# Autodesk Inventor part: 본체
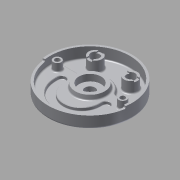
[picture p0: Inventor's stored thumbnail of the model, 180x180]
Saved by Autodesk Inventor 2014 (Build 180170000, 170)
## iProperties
Created: 2015-06
Part Number: 본체
Material: 알루미늄 6061
Document SubType Name: Modeling
Designer: MYHOME
Mass: 1071.21 g
Surface Area: 1035.4 cm^2
Volume: 395.281 cm^3
Density: 2.71 g/cm^3
Appearance: 알루미늄 - 평지
Author: MYHOME
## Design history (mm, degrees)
sketch "스케치1"
  geometry: C1 r 95 at (0, 0); C2 r 90 at (0, 0); 1 further point
  constraints: 2 centre point, 2 coincident
  dimensions: "d0" = 190 diameter of C1; "d1" = 180 diameter of C2
extrude "돌출1" new body sketch "스케치1" distance "d2" = 32; taper "d3" = 0 deg
extrude "돌출2" join sketch "스케치1" distance "d4" = 7; taper "d5" = 0 deg
sketch "스케치2"
  geometry: L1 (-88.566, 16)-(-38.833, 16); L2 (38.833, 16)-(88.566, 16); A1 r 90 centre (0, 0) between (-88.566, 16) and (88.566, 16) reference; A2 r 42 centre (0, 0) between (38.833, 16) and (-38.833, 16)
  constraints: 4 end point, 4 point on circle, 1 centre point, 1 coincident, 1 collinear, 1 horizontal
  dimensions: "d7" = 84 diameter of A2; "d8" = 16 distance from line of L2 A2.centre; "d9" = 16 distance from line of A1.centre L1
extrude "돌출3" join sketch "스케치2" distance "d10" = 7; taper "d11" = 0 deg
fillet "모깎기1" dims "d12" = 10
sketch "스케치3"
  geometry: C1 r 15 at (-40, 52); C2 r 15 at (40, 52); A1 r 90 centre (0, 0) between (85.114, 29.25) and (-85.114, 29.25) reference
  constraints: 2 centre point, 1 horizontal alignment
  dimensions: "d13" = 30 diameter of C1; "d14" = 30 diameter of C2; "d15" = 80 distance of C2.centre C1.centre; "d16" = 40 horizontal distance of A1.centre C2.centre; "d17" = 52 vertical distance of A1.centre C2.centre
extrude "돌출4" join sketch "스케치3" distance "d18" = 25; taper "d19" = 0 deg
sketch "스케치4"
  geometry: C1 r 15 at (0, 0) reference; C2 r 15 at (80, 0) reference; C3 r 10 at (80, 0); C4 r 10 at (0, 0); 1 further point
  constraints: 2 centre point, 2 coincident
  dimensions: "d20" = 20 diameter of C3; "d21" = 20 diameter of C4
extrude "돌출5" cut sketch "스케치4" stored distance "d22" = 25; taper "d23" = 0 deg
sketch "스케치5"
  geometry: L1 (6, -15)-(-6, -15); L2 (-6, -15)-(-6, 15); L3 (-6, 15)-(6, 15); L4 (6, 15)-(6, -15); L5 (6, -15)-(-6, 15); L6 (-6, -15)-(6, 15); L7 (95, -6)-(65, -6); L8 (65, -6)-(65, 6); L9 (65, 6)-(95, 6); L10 (95, 6)-(95, -6); L11 (95, -6)-(65, 6); L12 (65, -6)-(95, 6); C1 r 10 at (80, 0) reference; 5 further points
  constraints: 24 end point, 6 midpoint, 4 parallel, 2 horizontal, 2 perpendicular, 1 horizontal alignment, 1 vertical alignment, 2 other
  dimensions: "d24" = 12 distance between parallel lines of L7 L9; "d25" = 12 distance between parallel lines of L4 L2
extrude "돌출6" cut sketch "스케치5" distance "d26" = 3; taper "d27" = 0 deg
sketch "스케치6"
  geometry: L1 (-45.033, 16)-(-75.657, 16) reference; L2 (-59, -19)-(-41, -19); L3 (41, -19)-(59, -19); L4 (50, -19)-(50, -14); L5 (41, -19)-(41, -14); L6 (59, -19)-(59, -14); L7 (-50, -19)-(-50, -14); L8 (-41, -19)-(-41, -14); L9 (-59, -19)-(-59, -14); A1 r 90 centre (0, 0) between (-85.114, 29.25) and (85.114, 29.25) reference; A2 r 50 centre (0, -19) between (-50, -19) and (50, -19); A3 r 59 centre (0, -19) between (-59, -19) and (59, -19); A4 r 41 centre (0, -19) between (-41, -19) and (41, -19); A5 r 9 centre (-50, -19) between (-41, -19) and (-59, -19); A6 r 9 centre (50, -19) between (59, -19) and (41, -19); A7 r 9 centre (50, -14) between (41, -14) and (59, -14); A8 r 9 centre (-50, -14) between (-41, -14) and (-59, -14)
  constraints: 16 end point, 14 point on circle, 10 tangent, 7 centre point, 4 horizontal alignment, 2 coincident, 1 collinear, 1 midpoint, 1 parallel, 1 perpendicular, 1 vertical alignment
  dimensions: "d28" = 19 distance of A1.centre A2.centre; "d29" = 59 radius of A3; "d30" = 41 radius of A4; "d41" = 5 distance of L4.start L4.end; "d42" = 18 diameter of A7; "d44" = 5 distance of L7.start L7.end; "d45" = 18 diameter of A8
extrude "돌출7" cut sketch "스케치6" distance "d46" = 7; taper "d47" = 0 deg
chamfer "모따기1" distance "d48" = 1; stored, may be unused: second distance "d49" = 2, angle "d50" = 45 deg
fillet "모깎기2" dims "d51" = 1
sketch "스케치7"
  geometry: C1 r 35 at (0, 0); A1 r 42 centre (0, 0) between (36.373, 21) and (-36.373, 21) reference
  constraints: 1 centre point, 1 coincident
  dimensions: "d52" = 70 diameter of C1
extrude "돌출8" join sketch "스케치7" distance "d53" = 10; taper "d54" = -10 deg
fillet "모깎기3" dims "d55" = 3
sketch "스케치8"
  geometry: C1 r 9 at (-74, 0); C2 r 9 at (74, 0); A1 r 90 centre (0, 0) between (-85.114, 29.25) and (85.114, 29.25) reference
  constraints: 2 centre point, 2 horizontal alignment
  dimensions: "d69" = 18 diameter of C1; "d70" = 18 diameter of C2; "d71" = 148 distance of C2.centre C1.centre; "d72" = 74 distance of A1.centre C2.centre
extrude "돌출9" join sketch "스케치8" stored distance "d73" = 10; taper "d74" = 0 deg
fillet "모깎기5" dims "d75" = 3
sketch "스케치9"
  geometry: C1 r 9 at (74, 0) reference
hole "구멍2" sketch "스케치9" at (74, 0) diameter "d76" = 11; stored, may be unused: countersink angle "d80" = 90 deg, drill point angle "d82" = 118 deg; dims "d77" = 6, "d78" = 18, "d79" = 11, "d81" = 8
sketch "스케치10"
  geometry: C1 r 9 at (-74, 0) reference
hole "구멍3" sketch "스케치10" at (-74, 0) diameter "d83" = 11; stored, may be unused: countersink angle "d87" = 90 deg, drill point angle "d89" = 118 deg; dims "d84" = 6, "d85" = 18, "d86" = 11, "d88" = 8
fillet "모깎기7" dims "d95" = 3
fillet "모깎기8" dims "d96" = 5
fillet "모깎기9" dims "d97" = 3
sketch "스케치13"
  geometry: C1 r 90 at (0, 0) reference; A1 r 68 centre (0, 0) between (0, -68) and (68, 0)
  constraints: 2 point on circle, 1 centre point, 1 coincident, 1 other
  dimensions: "d100" = 68 radius of A1
feature "엠보싱1" sketch "스케치13" dims "d0" = 190, "d1" = 180, "d101" = 0.5, "d102" = 0
fillet "모깎기10" dims "d111" = 3
sketch "스케치17"
  geometry: C1 r 90 at (0, 0) reference; C2 r 26 at (0, 0)
  constraints: 1 centre point, 1 coincident
  dimensions: "d115" = 52 diameter of C2
extrude "돌출14" join sketch "스케치17" distance "d116" = 12; taper "d117" = -15 deg
hole "구멍4" diameter "d120" = 23; stored, may be unused: countersink angle "d124" = 90 deg, drill point angle "d126" = 118 deg; dims "d118" = 10, "d119" = 10, "d121" = 6, "d122" = 50, "d123" = 15, "d125" = 8
fillet "모깎기11" dims "d127" = 3
sketch "스케치20"
  geometry: L1 (0, 0)-(-94.075, -13.221); L2 (0, 0)-(94.075, -13.221); L3 (-95, 0)-(95, 0); A1 r 90 centre (0, 0) between (-89.124, -12.526) and (89.124, -12.526) reference; A2 r 95 centre (0, 0) between (-94.075, -13.221) and (94.075, -13.221) reference; 2 further points
  constraints: 6 end point, 6 point on circle, 2 coincident, 2 point on line, 1 horizontal, 1 midpoint
  dimensions: "d128" = 8 deg angle of L2 L3; "d129" = 8 deg angle of L3 L1
extrude "돌출15" cut sketch "스케치20" distance "d130" = 5; taper "d131" = 0 deg
fillet "모깎기12" dims "d132" = 3
chamfer "모따기4" distance "d133" = 1; stored, may be unused: second distance "d134" = 2, angle "d135" = 45 deg
fillet "모깎기13" dims "d136" = 0.3
node "솔리드1"
node "투영된 루프1"
node "투영된 루프2"
node "투영된 루프3"
node "투영된 루프4"
other parameters: "d99" = 136
